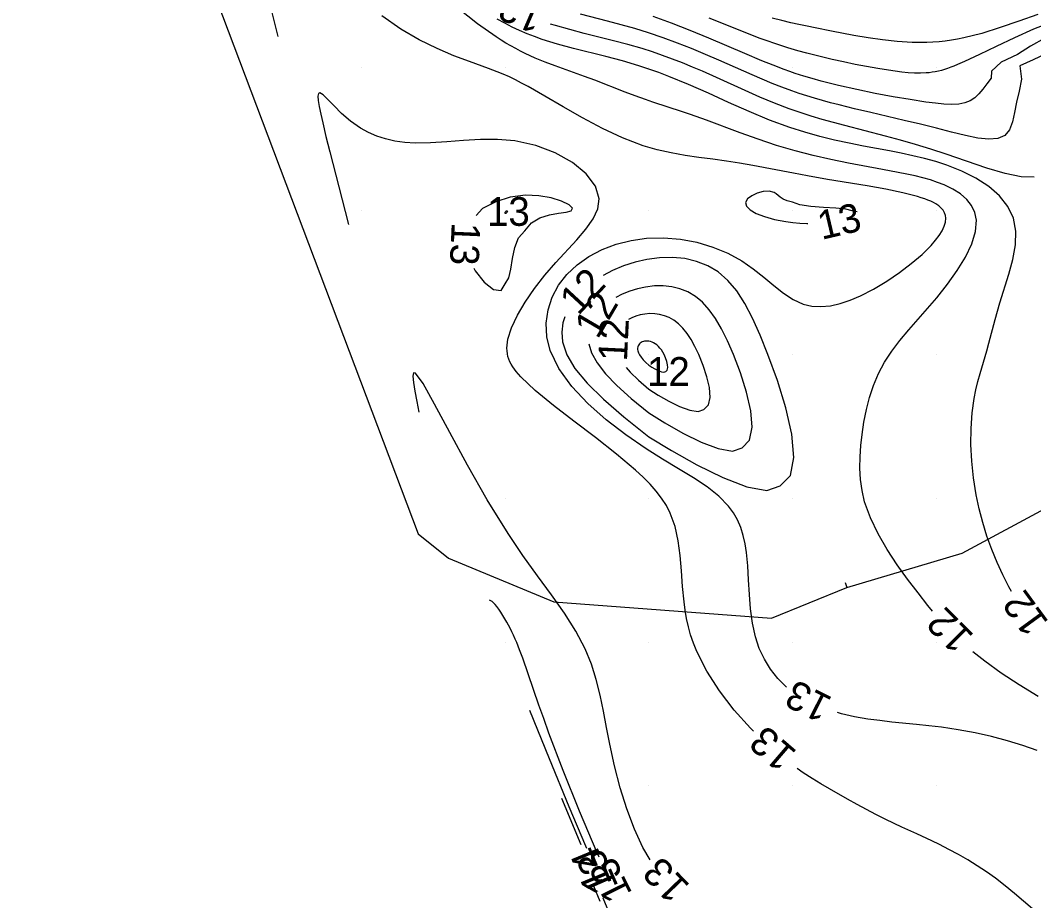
# Model space of a CAD drawing. Extents: x 2602990 to 2605851, y 618069 to 619180.
# Drawn here: x 2603096.3 to 2603166.8, y 618172 to 618233.3 of the extents above; entities that cross this region are included whole.
import ezdxf

# ---------------------------------------------------------------- set-up
doc = ezdxf.new("R2010")
doc.units = 0
for name, color, linetype in [('DTM Contours Major', 7, 'Continuous'), ('DTM Contours Major Text', 7, 'Continuous'), ('DTM Contours Minor', 7, 'Continuous'), ('DTM Contours Minor Text', 7, 'Continuous'), ('Exist DTM QL2 LIDAR Elevation Point', 7, 'Continuous'), ('PH Exist DTM Obscure Area', 7, 'Continuous')]:
    doc.layers.add(name, color=color, linetype=linetype)

msp = doc.modelspace()

# ---------------------------------------------------------------- linework, layer by layer
at = {"layer": 'DTM Contours Major'}
for points in [[(2603166.793, 618222.356), (2603165.896, 618222.361), (2603164.78, 618222.594), (2603163.501, 618222.984), (2603160.676, 618223.959), (2603159.61, 618224.302), (2603158.549, 618224.621), (2603157.499, 618224.919), (2603156.462, 618225.201), (2603153.638, 618225.94), (2603152.843, 618226.153), (2603152.06, 618226.372), (2603151.287, 618226.601), (2603150.521, 618226.845), (2603149.758, 618227.11), (2603148.738, 618227.501), (2603147.721, 618227.925), (2603146.709, 618228.37), (2603144.709, 618229.277), (2603143.723, 618229.714), (2603143.028, 618230.012), (2603142.336, 618230.296), (2603141.643, 618230.567), (2603140.948, 618230.823), (2603140.245, 618231.064), (2603139.533, 618231.29), (2603138.542, 618231.575), (2603137.534, 618231.841), (2603135.501, 618232.352), (2603134.492, 618232.615), (2603133.499, 618232.897), (2603133.157, 618233.003)], [(2603143.827, 618206.173), (2603144.143, 618206.495), (2603144.256, 618207.025), (2603144.206, 618207.703), (2603144.033, 618208.465), (2603143.775, 618209.251), (2603143.47, 618210), (2603143.206, 618210.556), (2603142.934, 618211.046), (2603142.654, 618211.471), (2603142.364, 618211.835), (2603142.061, 618212.139), (2603141.744, 618212.386), (2603141.422, 618212.572), (2603141.09, 618212.709), (2603140.749, 618212.8), (2603140.404, 618212.848), (2603140.057, 618212.855), (2603139.713, 618212.824), (2603139.403, 618212.763), (2603139.101, 618212.675), (2603138.814, 618212.56), (2603138.577, 618212.436)], [(2603138.419, 618209.094), (2603138.708, 618208.77), (2603139.288, 618208.213), (2603140, 618207.604), (2603140.645, 618207.187), (2603141.379, 618206.763), (2603142.134, 618206.39), (2603142.839, 618206.129), (2603143.427, 618206.037), (2603143.827, 618206.173)]]:
    msp.add_lwpolyline(points, dxfattribs=at)
at = {"layer": 'DTM Contours Minor'}
for points in [[(2603112.029, 618240.787), (2603114.197, 618232.141)], [(2603159.727, 618192.151), (2603159.404, 618192.549), (2603158.726, 618193.413), (2603158, 618194.367), (2603157.27, 618195.378), (2603156.571, 618196.435), (2603155.938, 618197.524), (2603155.406, 618198.634), (2603155.009, 618199.751), (2603154.827, 618200.537), (2603154.719, 618201.321), (2603154.675, 618202.104), (2603154.686, 618202.885), (2603154.742, 618203.666), (2603154.831, 618204.446), (2603154.962, 618205.311), (2603155.132, 618206.172), (2603155.351, 618207.023), (2603155.629, 618207.861), (2603155.975, 618208.68), (2603156.398, 618209.476), (2603156.898, 618210.24), (2603157.465, 618210.985), (2603158.081, 618211.72), (2603159.383, 618213.198), (2603160.034, 618213.957), (2603160.779, 618214.896), (2603161.454, 618215.848), (2603162.026, 618216.792), (2603162.462, 618217.706), (2603162.727, 618218.566), (2603162.79, 618219.35), (2603162.684, 618219.889), (2603162.453, 618220.373), (2603162.11, 618220.804), (2603161.668, 618221.185), (2603161.142, 618221.518), (2603160.545, 618221.807), (2603160.079, 618221.988), (2603159.584, 618222.151), (2603159.061, 618222.299), (2603158.513, 618222.434), (2603157.939, 618222.561), (2603157.341, 618222.683), (2603156.24, 618222.892), (2603153.885, 618223.33), (2603152.659, 618223.577), (2603151.419, 618223.855), (2603150.18, 618224.174), (2603148.876, 618224.563), (2603147.597, 618224.99), (2603146.352, 618225.437), (2603143.997, 618226.314), (2603142.904, 618226.709), (2603142.349, 618226.899), (2603140.271, 618227.578), (2603139.776, 618227.746), (2603139.057, 618228.003), (2603138.346, 618228.27), (2603136.232, 618229.089), (2603135.525, 618229.354), (2603133.487, 618230.085), (2603132.796, 618230.349), (2603132.099, 618230.638), (2603131.396, 618230.96), (2603131.066, 618231.124), (2603130.734, 618231.298), (2603130.398, 618231.483), (2603130.059, 618231.681), (2603129.716, 618231.891), (2603129.367, 618232.115), (2603128.082, 618233.027), (2603126.741, 618234.091)], [(2603149.57, 618186.868), (2603149.551, 618186.883), (2603148.973, 618187.459), (2603148.467, 618188.101), (2603148.034, 618188.802), (2603147.68, 618189.557), (2603147.408, 618190.363), (2603147.198, 618191.316), (2603147.068, 618192.306), (2603146.99, 618193.313), (2603146.935, 618194.317), (2603146.876, 618195.299), (2603146.785, 618196.24), (2603146.691, 618196.843), (2603146.563, 618197.42), (2603146.391, 618197.969), (2603146.169, 618198.492), (2603145.889, 618198.989), (2603145.542, 618199.461), (2603144.869, 618200.145), (2603144.046, 618200.791), (2603143.102, 618201.422), (2603142.061, 618202.061), (2603140.952, 618202.729), (2603139.802, 618203.448), (2603138.39, 618204.413), (2603137.017, 618205.469), (2603135.745, 618206.6), (2603134.634, 618207.79), (2603133.747, 618209.023), (2603133.144, 618210.28), (2603132.907, 618211.241), (2603132.858, 618212.191), (2603132.984, 618213.115), (2603133.273, 618213.998), (2603133.714, 618214.824), (2603134.294, 618215.577), (2603135.007, 618216.25), (2603135.831, 618216.828), (2603136.746, 618217.307), (2603137.732, 618217.681), (2603138.769, 618217.947), (2603139.838, 618218.099), (2603141.015, 618218.132), (2603142.188, 618218.034), (2603143.337, 618217.815), (2603144.445, 618217.483), (2603145.492, 618217.048), (2603146.459, 618216.519), (2603147.261, 618215.967), (2603148.002, 618215.384), (2603148.699, 618214.809), (2603149.373, 618214.281), (2603150.043, 618213.839), (2603150.728, 618213.522), (2603151.337, 618213.375), (2603151.971, 618213.337), (2603152.627, 618213.4), (2603153.306, 618213.554), (2603154.004, 618213.79), (2603154.721, 618214.097), (2603155.634, 618214.564), (2603156.545, 618215.107), (2603157.429, 618215.703), (2603158.256, 618216.332), (2603159, 618216.972), (2603159.632, 618217.602), (2603159.939, 618217.956), (2603160.195, 618218.298), (2603160.398, 618218.625), (2603160.545, 618218.935), (2603160.632, 618219.227), (2603160.658, 618219.499), (2603160.634, 618219.692), (2603160.572, 618219.873), (2603160.474, 618220.042), (2603160.339, 618220.2), (2603160.169, 618220.348), (2603159.964, 618220.486), (2603159.795, 618220.58), (2603159.609, 618220.67), (2603159.405, 618220.757), (2603159.185, 618220.839), (2603158.948, 618220.92), (2603158.694, 618220.997), (2603157.672, 618221.259), (2603156.491, 618221.503), (2603155.195, 618221.737), (2603152.426, 618222.195), (2603151.041, 618222.434), (2603150.053, 618222.616), (2603147.226, 618223.16), (2603146.312, 618223.322), (2603145.406, 618223.467), (2603144.444, 618223.6), (2603143.482, 618223.726), (2603142.518, 618223.863), (2603141.55, 618224.031), (2603140.575, 618224.248), (2603139.592, 618224.532), (2603138.176, 618225.074), (2603136.762, 618225.742), (2603135.374, 618226.484), (2603134.034, 618227.251), (2603132.768, 618227.992), (2603131.597, 618228.658), (2603131.148, 618228.898), (2603130.715, 618229.119), (2603130.293, 618229.321), (2603129.869, 618229.51), (2603129.446, 618229.685), (2603128.836, 618229.919), (2603127.532, 618230.39), (2603126.443, 618230.8), (2603125.265, 618231.295), (2603124.022, 618231.904), (2603122.736, 618232.656), (2603121.429, 618233.579)], [(2603165.221, 618193.523), (2603165.036, 618193.85), (2603164.617, 618194.673), (2603164.219, 618195.54), (2603163.851, 618196.437), (2603163.517, 618197.361), (2603163.22, 618198.307), (2603162.966, 618199.273), (2603162.756, 618200.254), (2603162.571, 618201.424), (2603162.454, 618202.594), (2603162.401, 618203.748), (2603162.414, 618204.869), (2603162.49, 618205.941), (2603162.628, 618206.948), (2603162.747, 618207.551), (2603162.885, 618208.127), (2603163.037, 618208.68), (2603163.509, 618210.272), (2603163.657, 618210.806), (2603164.088, 618212.45), (2603164.246, 618213.024), (2603164.419, 618213.614), (2603165.047, 618215.606), (2603165.317, 618216.624), (2603165.493, 618217.628), (2603165.524, 618218.594), (2603165.361, 618219.5), (2603164.976, 618220.313), (2603164.391, 618221.046), (2603163.638, 618221.7), (2603162.754, 618222.273), (2603161.773, 618222.768), (2603160.728, 618223.182), (2603159.955, 618223.432), (2603159.168, 618223.649), (2603158.368, 618223.839), (2603157.558, 618224.01), (2603156.738, 618224.169), (2603154.921, 618224.511), (2603153.921, 618224.711), (2603152.911, 618224.931), (2603151.89, 618225.181), (2603150.858, 618225.468), (2603149.814, 618225.801), (2603148.399, 618226.325), (2603146.973, 618226.917), (2603145.549, 618227.546), (2603144.138, 618228.183), (2603142.75, 618228.797), (2603141.397, 618229.358), (2603140.692, 618229.627), (2603139.995, 618229.874), (2603139.301, 618230.1), (2603138.157, 618230.435), (2603137.013, 618230.737), (2603134.753, 618231.305), (2603133.651, 618231.606), (2603132.578, 618231.939), (2603132.047, 618232.126), (2603131.522, 618232.328), (2603131.003, 618232.548), (2603130.486, 618232.79), (2603129.971, 618233.055), (2603129.454, 618233.347)], [(2603167.609, 618230.94), (2603166.731, 618230.522), (2603165.807, 618230.099), (2603165.91, 618229.158), (2603165.768, 618228.336), (2603165.579, 618227.578), (2603165.436, 618226.851), (2603165.288, 618226.195), (2603165.081, 618225.65), (2603164.764, 618225.256), (2603164.284, 618225.037), (2603163.653, 618224.983), (2603162.89, 618225.061), (2603162.015, 618225.237), (2603161.047, 618225.478), (2603160.005, 618225.748), (2603158.899, 618226.025), (2603157.756, 618226.298), (2603155.444, 618226.84), (2603154.314, 618227.11), (2603153.227, 618227.379), (2603152.643, 618227.53), (2603152.077, 618227.683), (2603151.527, 618227.84), (2603150.988, 618228.002), (2603150.46, 618228.171), (2603149.94, 618228.349), (2603149.251, 618228.603), (2603148.567, 618228.875), (2603147.884, 618229.161), (2603147.196, 618229.459), (2603144.871, 618230.488), (2603143.928, 618230.894), (2603142.964, 618231.295), (2603141.982, 618231.683), (2603140.985, 618232.051), (2603139.979, 618232.392), (2603139.029, 618232.684), (2603138.077, 618232.952), (2603137.127, 618233.203), (2603135.248, 618233.684)], [(2603167.538, 618232.021), (2603166.538, 618231.472), (2603165.632, 618230.882), (2603164.501, 618230.356), (2603163.835, 618229.718), (2603163.818, 618229.239), (2603163.504, 618228.842), (2603163.221, 618228.474), (2603162.949, 618228.147), (2603162.666, 618227.871), (2603162.351, 618227.656), (2603161.979, 618227.509), (2603161.551, 618227.429), (2603161.068, 618227.406), (2603160.527, 618227.429), (2603159.928, 618227.489), (2603159.271, 618227.577), (2603158.179, 618227.742), (2603156.988, 618227.943), (2603155.737, 618228.176), (2603154.462, 618228.437), (2603153.198, 618228.724), (2603151.982, 618229.032), (2603151.365, 618229.204), (2603150.767, 618229.383), (2603150.182, 618229.572), (2603149.796, 618229.704), (2603149.411, 618229.842), (2603148.638, 618230.134), (2603147.849, 618230.449), (2603146.668, 618230.943), (2603144.167, 618232.013), (2603142.878, 618232.549), (2603141.583, 618233.059), (2603140.298, 618233.524)], [(2603168.141, 618233.181), (2603166.763, 618232.635), (2603165.426, 618232.045), (2603164.159, 618231.45), (2603162.992, 618230.89), (2603161.955, 618230.401), (2603161.458, 618230.179), (2603161.224, 618230.081), (2603160.997, 618229.992), (2603160.777, 618229.912), (2603160.563, 618229.841), (2603160.347, 618229.779), (2603160.135, 618229.726), (2603159.924, 618229.682), (2603159.714, 618229.647), (2603159.504, 618229.619), (2603159.292, 618229.6), (2603158.887, 618229.583), (2603158.47, 618229.588), (2603158.041, 618229.614), (2603157.597, 618229.657), (2603157.137, 618229.714), (2603156.66, 618229.784), (2603155.917, 618229.905), (2603155.143, 618230.044), (2603154.349, 618230.198), (2603153.546, 618230.366), (2603152.744, 618230.543), (2603151.63, 618230.808), (2603150.988, 618230.972), (2603150.351, 618231.146), (2603149.656, 618231.352), (2603148.889, 618231.599), (2603148.091, 618231.877), (2603147.675, 618232.03), (2603146.575, 618232.453), (2603144.201, 618233.403)], [(2603167.049, 618233.678), (2603165.739, 618233.211), (2603164.438, 618232.758), (2603163.159, 618232.354), (2603161.915, 618232.035), (2603161.476, 618231.947), (2603161.042, 618231.874), (2603160.611, 618231.815), (2603160.183, 618231.771), (2603159.757, 618231.739), (2603159.33, 618231.721), (2603158.304, 618231.726), (2603157.277, 618231.79), (2603156.256, 618231.9), (2603155.248, 618232.045), (2603154.259, 618232.212), (2603152.709, 618232.502), (2603151.562, 618232.729), (2603150.999, 618232.847), (2603150.441, 618232.969), (2603149.885, 618233.096), (2603149.237, 618233.253), (2603148.587, 618233.42)], [(2603147.277, 618183.801), (2603147.073, 618184), (2603145.938, 618185.262), (2603144.906, 618186.595), (2603144.021, 618187.963), (2603143.327, 618189.335), (2603143.097, 618189.916), (2603142.906, 618190.493), (2603142.75, 618191.067), (2603142.624, 618191.64), (2603142.525, 618192.214), (2603142.447, 618192.789), (2603142.346, 618193.87), (2603142.27, 618194.949), (2603142.183, 618196.013), (2603142.048, 618197.047), (2603141.828, 618198.039), (2603141.488, 618198.976), (2603141.215, 618199.5), (2603140.889, 618200.007), (2603140.509, 618200.5), (2603140.078, 618200.987), (2603139.598, 618201.473), (2603139.068, 618201.964), (2603137.741, 618203.082), (2603136.281, 618204.224), (2603134.787, 618205.361), (2603133.357, 618206.464), (2603132.091, 618207.506), (2603131.089, 618208.457), (2603130.925, 618208.638), (2603130.776, 618208.815), (2603130.643, 618208.989), (2603130.525, 618209.161), (2603130.422, 618209.332), (2603130.335, 618209.502), (2603130.257, 618209.688), (2603130.197, 618209.876), (2603130.156, 618210.066), (2603130.132, 618210.261), (2603130.125, 618210.46), (2603130.135, 618210.665), (2603130.159, 618210.866), (2603130.199, 618211.073), (2603130.453, 618211.875), (2603130.864, 618212.745), (2603131.404, 618213.658), (2603132.047, 618214.591), (2603132.766, 618215.519), (2603133.535, 618216.419), (2603134.988, 618217.988), (2603135.62, 618218.724), (2603136.122, 618219.438), (2603136.446, 618220.139), (2603136.54, 618220.836), (2603136.278, 618221.724), (2603135.634, 618222.579), (2603134.679, 618223.362), (2603133.486, 618224.031), (2603132.126, 618224.547), (2603130.67, 618224.869), (2603129.478, 618224.972), (2603128.283, 618224.966), (2603127.099, 618224.895), (2603125.939, 618224.8), (2603124.816, 618224.726), (2603123.742, 618224.713), (2603123.024, 618224.761), (2603122.338, 618224.86), (2603121.685, 618225.01), (2603121.068, 618225.21), (2603120.487, 618225.459), (2603119.944, 618225.757), (2603119.244, 618226.251), (2603118.628, 618226.786), (2603118.102, 618227.306), (2603117.671, 618227.755), (2603117.34, 618228.077), (2603117.117, 618228.218), (2603117.019, 618228.172), (2603116.982, 618227.992), (2603117, 618227.687), (2603117.065, 618227.267), (2603117.171, 618226.741), (2603117.312, 618226.118), (2603117.538, 618225.171), (2603117.803, 618224.1), (2603118.421, 618221.682), (2603119.101, 618219.064)], [(2603150, 618220.597), (2603149.619, 618220.698), (2603149.341, 618220.819), (2603149.139, 618220.949), (2603148.854, 618221.193), (2603148.716, 618221.284), (2603148.373, 618221.369), (2603147.961, 618221.345), (2603147.536, 618221.233), (2603147.151, 618221.055), (2603146.862, 618220.832), (2603146.724, 618220.584), (2603146.784, 618220.321), (2603147.042, 618220.064), (2603147.472, 618219.82), (2603148.048, 618219.6), (2603148.745, 618219.411), (2603149.537, 618219.262), (2603150.01, 618219.199), (2603150.499, 618219.154), (2603150.998, 618219.126), (2603151.058, 618219.125)], [(2603131.378, 618218.622), (2603131.832, 618219.162), (2603132.425, 618219.51), (2603133.077, 618219.718), (2603133.709, 618219.835), (2603134.241, 618219.912), (2603134.594, 618220), (2603134.697, 618220.184), (2603134.451, 618220.425), (2603133.928, 618220.679), (2603133.199, 618220.905), (2603132.337, 618221.06), (2603131.412, 618221.099), (2603130.343, 618220.958), (2603129.344, 618220.624), (2603128.429, 618220.156), (2603127.994, 618219.685)], [(2603154.493, 618219.934), (2603154.148, 618220), (2603153.709, 618220.112), (2603152.996, 618220.185), (2603152.139, 618220.244), (2603151.267, 618220.315), (2603150.511, 618220.424), (2603150, 618220.597)], [(2603130.039, 618219.961), (2603130.071, 618219.986), (2603130.104, 618219.999), (2603130.132, 618220), (2603130.152, 618219.989), (2603130.158, 618219.967), (2603130.141, 618219.918), (2603130.101, 618219.862), (2603130.053, 618219.821), (2603130.038, 618219.814), (2603130.024, 618219.814), (2603130.013, 618219.82), (2603130.005, 618219.833), (2603130, 618219.855), (2603130.01, 618219.908), (2603130.028, 618219.945), (2603130.039, 618219.961)], [(2603127.834, 618216.008), (2603127.919, 618215.839), (2603128.548, 618215.041), (2603129.19, 618214.538), (2603129.717, 618214.46), (2603130, 618214.935), (2603130.251, 618215.339), (2603130.401, 618215.956), (2603130.52, 618216.691), (2603130.676, 618217.445), (2603130.939, 618218.121), (2603131.378, 618218.622)], [(2603149.136, 618200.864), (2603149.849, 618201.598), (2603150.083, 618202.849), (2603149.941, 618204.465), (2603149.525, 618206.296), (2603148.938, 618208.191), (2603148.283, 618210), (2603147.747, 618211.346), (2603147.217, 618212.532), (2603146.677, 618213.562), (2603146.11, 618214.439), (2603145.498, 618215.168), (2603144.824, 618215.752), (2603144.104, 618216.183), (2603143.323, 618216.49), (2603142.495, 618216.679), (2603141.632, 618216.76), (2603140.748, 618216.737), (2603139.856, 618216.619), (2603139.039, 618216.431), (2603138.24, 618216.174), (2603137.471, 618215.852), (2603136.821, 618215.509)], [(2603146.482, 618203.518), (2603146.999, 618204.05), (2603147.176, 618204.942), (2603147.082, 618206.089), (2603146.787, 618207.385), (2603146.362, 618208.724), (2603145.877, 618210), (2603145.469, 618210.949), (2603145.059, 618211.784), (2603144.639, 618212.509), (2603144.201, 618213.127), (2603143.737, 618213.641), (2603143.238, 618214.054), (2603142.717, 618214.361), (2603142.163, 618214.582), (2603141.585, 618214.722), (2603140.988, 618214.786), (2603140.381, 618214.779), (2603139.772, 618214.705), (2603139.216, 618214.583), (2603138.672, 618214.412), (2603138.15, 618214.196), (2603137.707, 618213.963)], [(2603134.155, 618212.639), (2603134.014, 618212.204), (2603133.934, 618211.551), (2603133.992, 618210.883), (2603134.291, 618209.982), (2603134.857, 618209.038), (2603135.701, 618208.022), (2603136.832, 618206.909), (2603138.261, 618205.671), (2603140, 618204.28), (2603141.565, 618203.335), (2603143.332, 618202.336), (2603145.137, 618201.438), (2603146.815, 618200.791), (2603148.202, 618200.549), (2603149.136, 618200.864)], [(2603135.813, 618210.742), (2603136.013, 618210.115), (2603136.406, 618209.421), (2603136.991, 618208.672), (2603137.779, 618207.852), (2603138.779, 618206.947), (2603140, 618205.942), (2603141.103, 618205.257), (2603142.352, 618204.544), (2603143.631, 618203.91), (2603144.824, 618203.457), (2603145.813, 618203.292), (2603146.482, 618203.518)], [(2603141.173, 618208.827), (2603141.273, 618208.929), (2603141.311, 618209.093), (2603141.299, 618209.299), (2603141.247, 618209.532), (2603141.165, 618209.771), (2603141.064, 618210), (2603140.971, 618210.172), (2603140.874, 618210.324), (2603140.771, 618210.458), (2603140.665, 618210.575), (2603140.555, 618210.674), (2603140.443, 618210.756), (2603140.332, 618210.821), (2603140.222, 618210.871), (2603140.111, 618210.908), (2603140.002, 618210.932), (2603139.895, 618210.942), (2603139.792, 618210.941), (2603139.701, 618210.93), (2603139.615, 618210.909), (2603139.534, 618210.879), (2603139.46, 618210.841), (2603139.394, 618210.794), (2603139.337, 618210.739), (2603139.29, 618210.677), (2603139.253, 618210.607), (2603139.229, 618210.531), (2603139.216, 618210.447), (2603139.218, 618210.357), (2603139.234, 618210.26), (2603139.28, 618210.123), (2603139.356, 618209.974), (2603139.463, 618209.814), (2603139.605, 618209.643), (2603139.783, 618209.46), (2603140, 618209.266), (2603140.198, 618209.131), (2603140.422, 618209), (2603140.652, 618208.887), (2603140.867, 618208.81), (2603141.048, 618208.785), (2603141.173, 618208.827)], [(2603140.078, 618174.854), (2603139.576, 618175.71), (2603138.988, 618176.988), (2603138.465, 618178.385), (2603138.007, 618179.863), (2603137.611, 618181.381), (2603137.276, 618182.901), (2603137.054, 618184.055), (2603136.841, 618185.187), (2603136.612, 618186.299), (2603136.341, 618187.392), (2603136.002, 618188.469), (2603135.57, 618189.529), (2603134.918, 618190.764), (2603134.129, 618192.004), (2603133.233, 618193.276), (2603132.261, 618194.606), (2603131.24, 618196.019), (2603130.201, 618197.542), (2603128.755, 618199.884), (2603127.385, 618202.298), (2603126.147, 618204.586), (2603125.097, 618206.55), (2603124.288, 618207.992), (2603123.775, 618208.715), (2603123.63, 618208.74), (2603123.584, 618208.504), (2603123.619, 618208.058), (2603123.714, 618207.455), (2603123.85, 618206.747), (2603124.005, 618205.987)], [(2603136.547, 618175.039), (2603136.409, 618175.331), (2603135.167, 618178.223), (2603134.029, 618181.067), (2603133.051, 618183.663), (2603132.685, 618184.674), (2603132.356, 618185.603), (2603131.221, 618188.878), (2603131.011, 618189.455), (2603130.809, 618189.971), (2603130.709, 618190.208), (2603130.591, 618190.472), (2603130.472, 618190.72), (2603130.354, 618190.954), (2603130.12, 618191.382), (2603129.849, 618191.839), (2603129.699, 618192.076), (2603129.558, 618192.286), (2603129.426, 618192.468), (2603129.306, 618192.617), (2603129.199, 618192.731), (2603129.143, 618192.781), (2603129.091, 618192.82), (2603128.997, 618192.873), (2603128.909, 618192.91)], [(2603167.071, 618186.201), (2603165.75, 618187.019), (2603164.512, 618187.841), (2603163.374, 618188.659), (2603162.542, 618189.32)], [(2603135.679, 618175.628), (2603135.603, 618175.803), (2603134.466, 618178.525), (2603133.092, 618181.87), (2603131.73, 618185.241)], [(2603166.999, 618182.451), (2603166.008, 618182.807), (2603164.949, 618183.131), (2603163.837, 618183.421), (2603162.689, 618183.674), (2603161.521, 618183.889), (2603160.348, 618184.065), (2603159.475, 618184.171), (2603158.608, 618184.262), (2603156.9, 618184.433), (2603156.06, 618184.529), (2603155.23, 618184.643), (2603154.305, 618184.803), (2603153.403, 618185.006), (2603153.114, 618185.089)], [(2603166.687, 618171.435), (2603165.437, 618172.49), (2603164.781, 618173.032), (2603164.104, 618173.56), (2603163.477, 618174.012), (2603162.837, 618174.438), (2603162.188, 618174.84), (2603161.533, 618175.218), (2603160.876, 618175.574), (2603160.22, 618175.907), (2603159.689, 618176.162), (2603158.635, 618176.645), (2603157.588, 618177.118), (2603157.067, 618177.361), (2603156.426, 618177.673), (2603155.783, 618177.999), (2603155.136, 618178.339), (2603154.482, 618178.692), (2603153.818, 618179.06), (2603152.555, 618179.775), (2603151.958, 618180.126), (2603151.351, 618180.499), (2603150.735, 618180.901), (2603150.308, 618181.199)], [(2603135.279, 618175.879), (2603133.956, 618179.121)], [(2603136.61, 618171.936), (2603136.181, 618173.001)], [(2603137.827, 618169.76), (2603136.81, 618172.183)]]:
    msp.add_lwpolyline(points, dxfattribs=at)
at = {"layer": 'Exist DTM QL2 LIDAR Elevation Point'}
for p, q in [((2603120, 618230), (2603120, 618230)), ((2603130, 618230), (2603130, 618230)), ((2603140, 618230), (2603140, 618230)), ((2603150, 618230), (2603150, 618230)), ((2603160, 618230), (2603160, 618230)), ((2603120, 618220), (2603120, 618220)), ((2603130, 618220), (2603130, 618220)), ((2603140, 618220), (2603140, 618220)), ((2603150, 618220), (2603150, 618220)), ((2603160, 618220), (2603160, 618220)), ((2603130, 618210), (2603130, 618210)), ((2603140, 618210), (2603140, 618210)), ((2603150, 618210), (2603150, 618210)), ((2603160, 618210), (2603160, 618210)), ((2603130, 618200), (2603130, 618200)), ((2603140, 618200), (2603140, 618200)), ((2603150, 618200), (2603150, 618200)), ((2603160, 618200), (2603160, 618200)), ((2603130, 618190), (2603130, 618190)), ((2603140, 618190), (2603140, 618190)), ((2603150, 618190), (2603150, 618190)), ((2603160, 618190), (2603160, 618190)), ((2603140, 618180), (2603140, 618180)), ((2603150, 618180), (2603150, 618180)), ((2603160, 618180), (2603160, 618180))]:
    msp.add_line(p, q, dxfattribs=at)
at = {"layer": 'PH Exist DTM Obscure Area'}
for points in [[(2603096.272, 618270.87), (2603123.953, 618197.536)], [(2603153.646, 618194.142), (2603153.781, 618193.789), (2603161.783, 618196.195), (2603173.94, 618202.717), (2603178.185, 618205.61), (2603186.003, 618208.957), (2603197.759, 618210.029), (2603207.704, 618206.033), (2603214.095, 618205.908), (2603236.88, 618213.413)], [(2603123.953, 618197.536), (2603126.067, 618195.847), (2603133.398, 618192.798), (2603148.523, 618191.658), (2603153.781, 618193.789)]]:
    msp.add_lwpolyline(points, dxfattribs=at)

# ---------------------------------------------------------------- texts
at = {"layer": 'DTM Contours Major Text'}
for rotation, p in [(156.57474, (2603132.868, 618234.088)), (87.29214, (2603138.474, 618209.501))]:
    msp.add_text('12', height=2, rotation=rotation, dxfattribs=at).set_placement(p)
at = {"layer": 'DTM Contours Minor Text'}
for s, p in [('13', (2603128.74, 618218.961)), ('12', (2603139.874, 618207.827))]:
    msp.add_text(s, height=2, dxfattribs=at).set_placement(p)
for s, rotation, p in [('13', 13.24888, (2603152.015, 618217.979)), ('13', 267.50802, (2603126.288, 618219.23)), ('12', 47.10896, (2603135.087, 618212.665)), ('12', 59.54948, (2603136.432, 618211.016)), ('12', 126.12631, (2603167.864, 618191.375)), ('12', 134.83783, (2603162.686, 618190.446)), ('13', 153.34433, (2603152.851, 618186.093)), ('13', 139.35585, (2603150.378, 618182.351)), ('14', 112.49042, (2603137.464, 618173.213)), ('13', 113.59038, (2603137.907, 618173.001)), ('13', 116.29593, (2603138.873, 618172.509)), ('13', 133.99259, (2603142.929, 618173.044))]:
    msp.add_text(s, height=2, rotation=rotation, dxfattribs=at).set_placement(p)

doc.saveas('drawing.dxf')
